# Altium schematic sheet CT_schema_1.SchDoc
size 511 x 447 mm
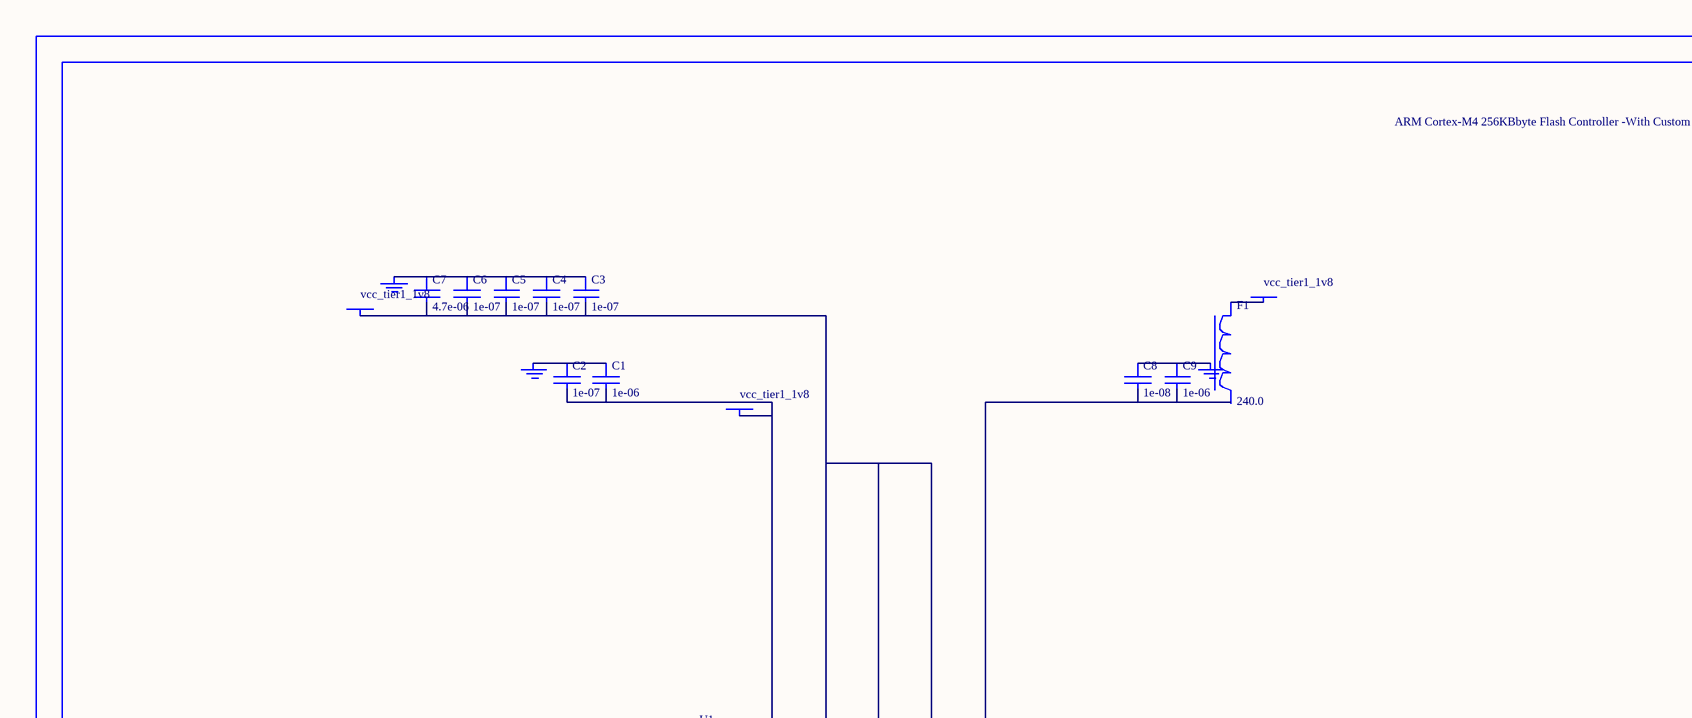
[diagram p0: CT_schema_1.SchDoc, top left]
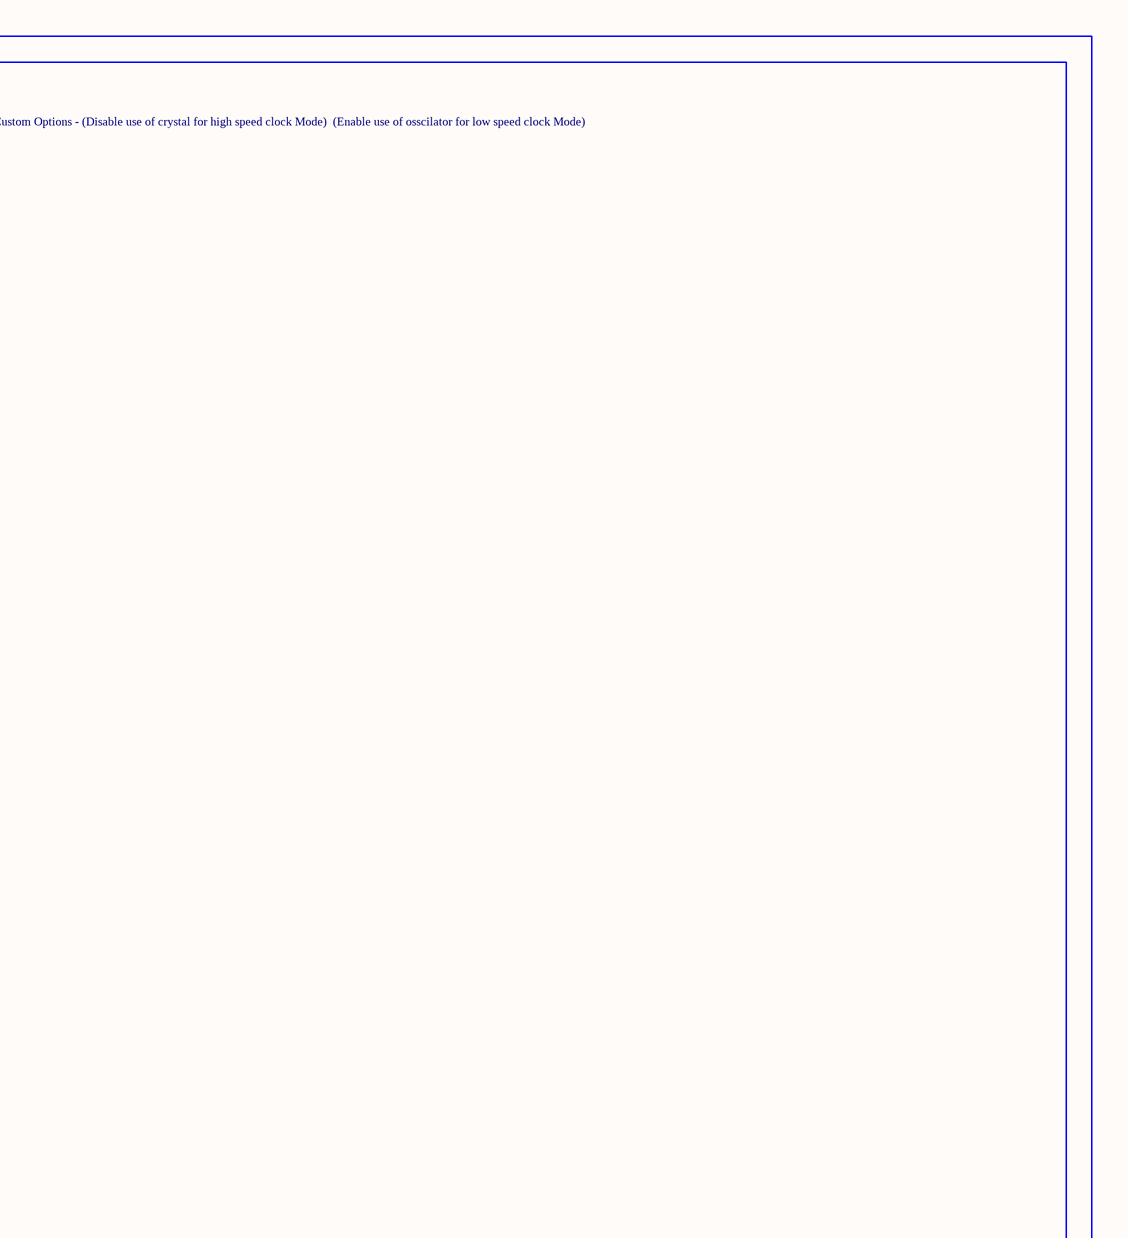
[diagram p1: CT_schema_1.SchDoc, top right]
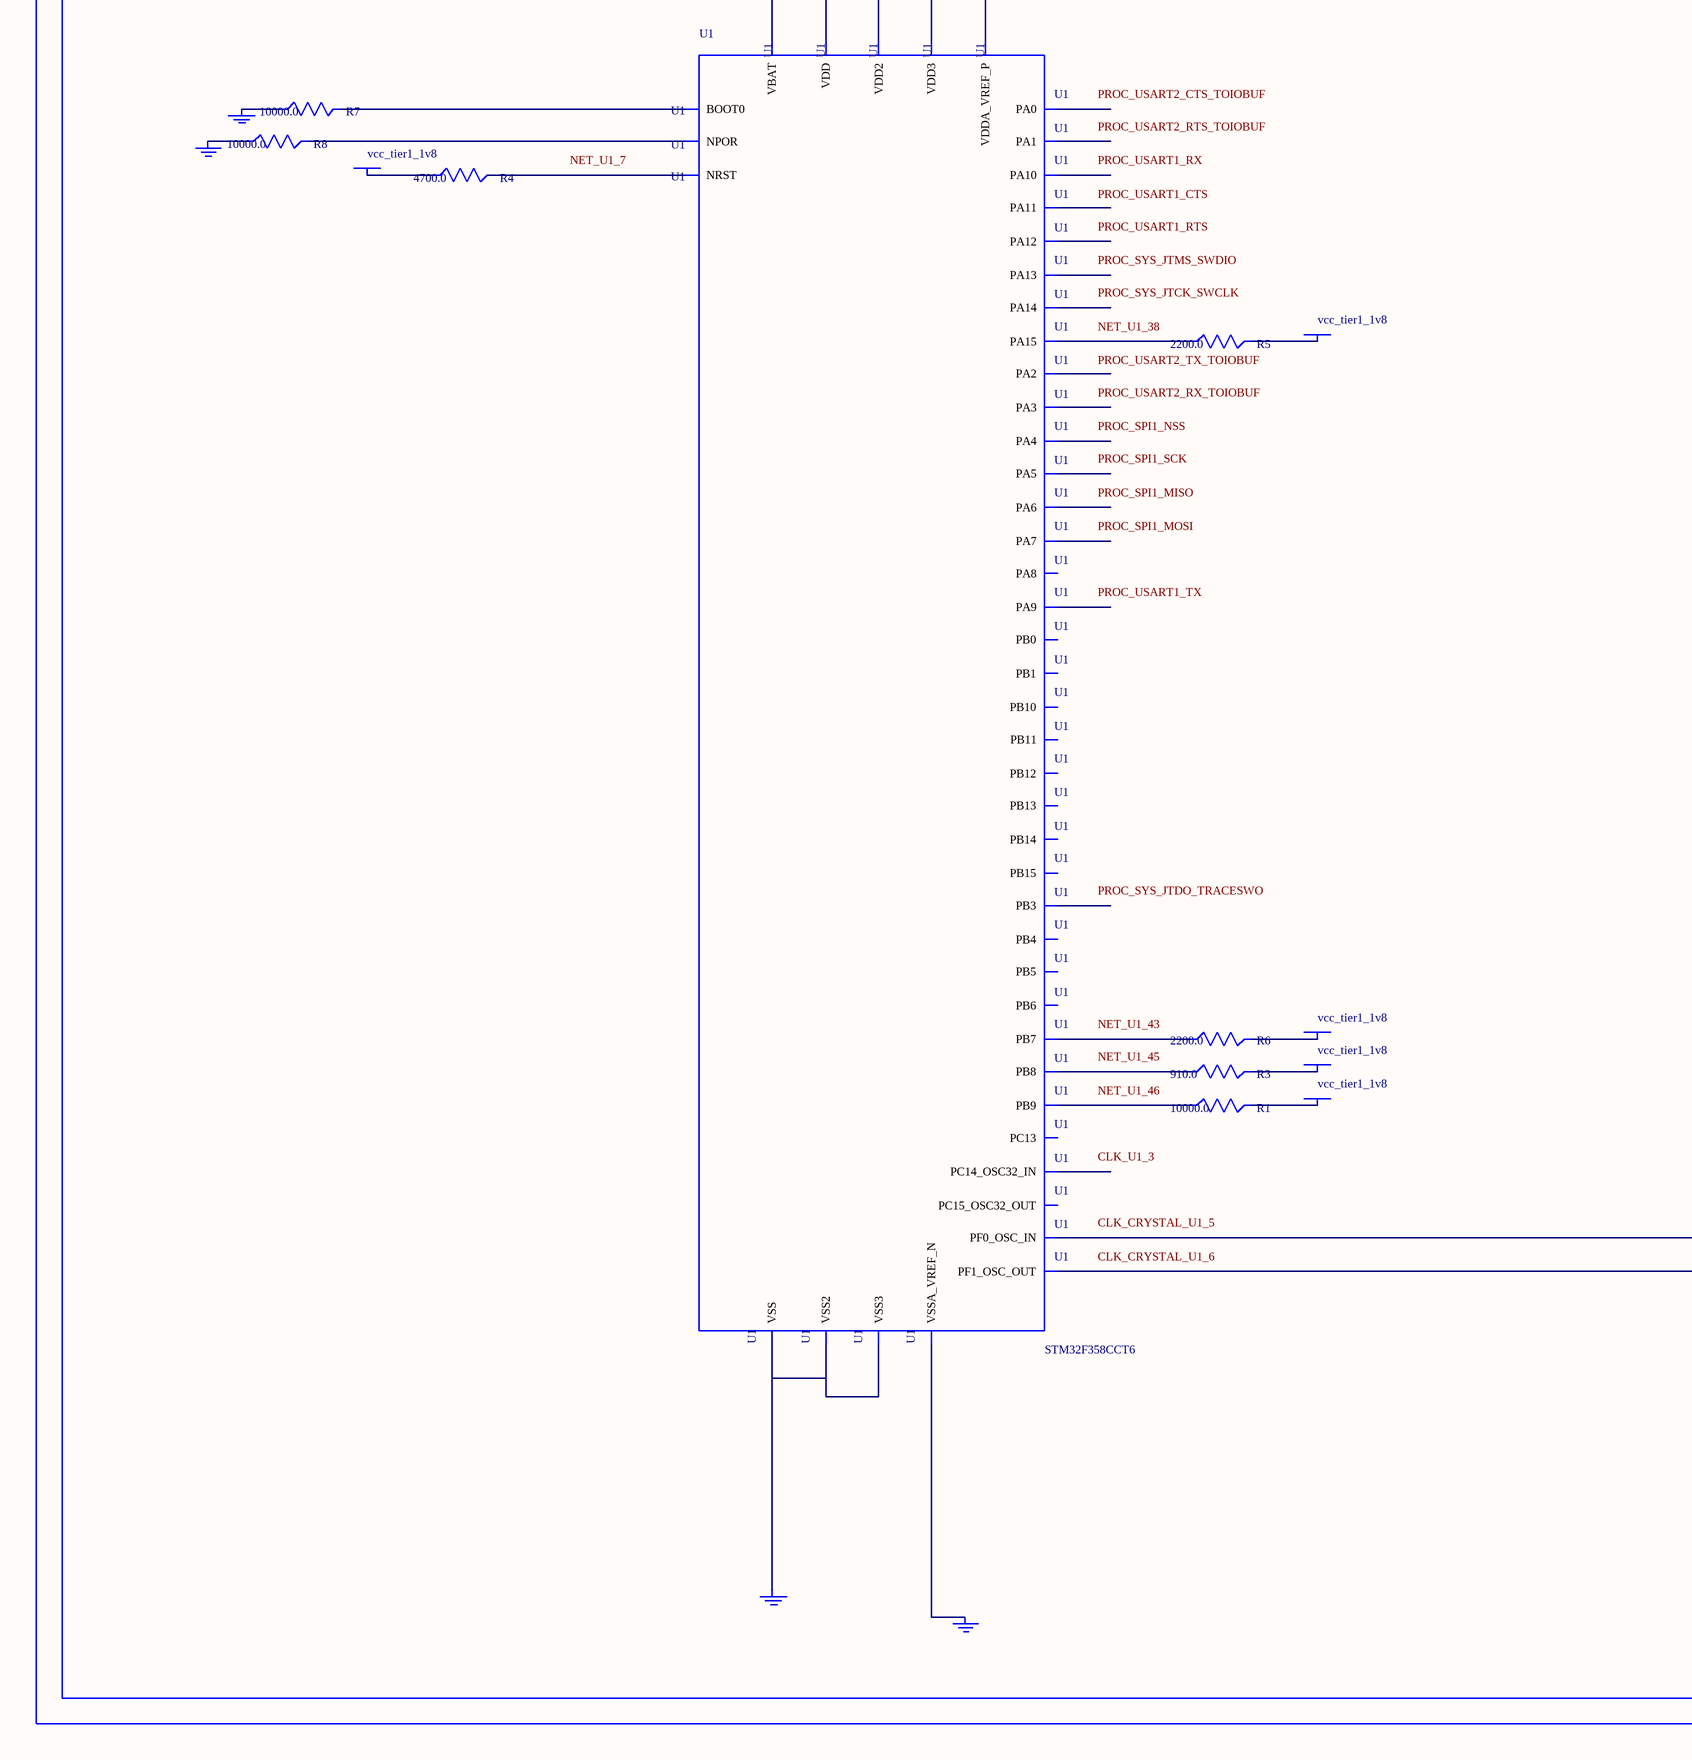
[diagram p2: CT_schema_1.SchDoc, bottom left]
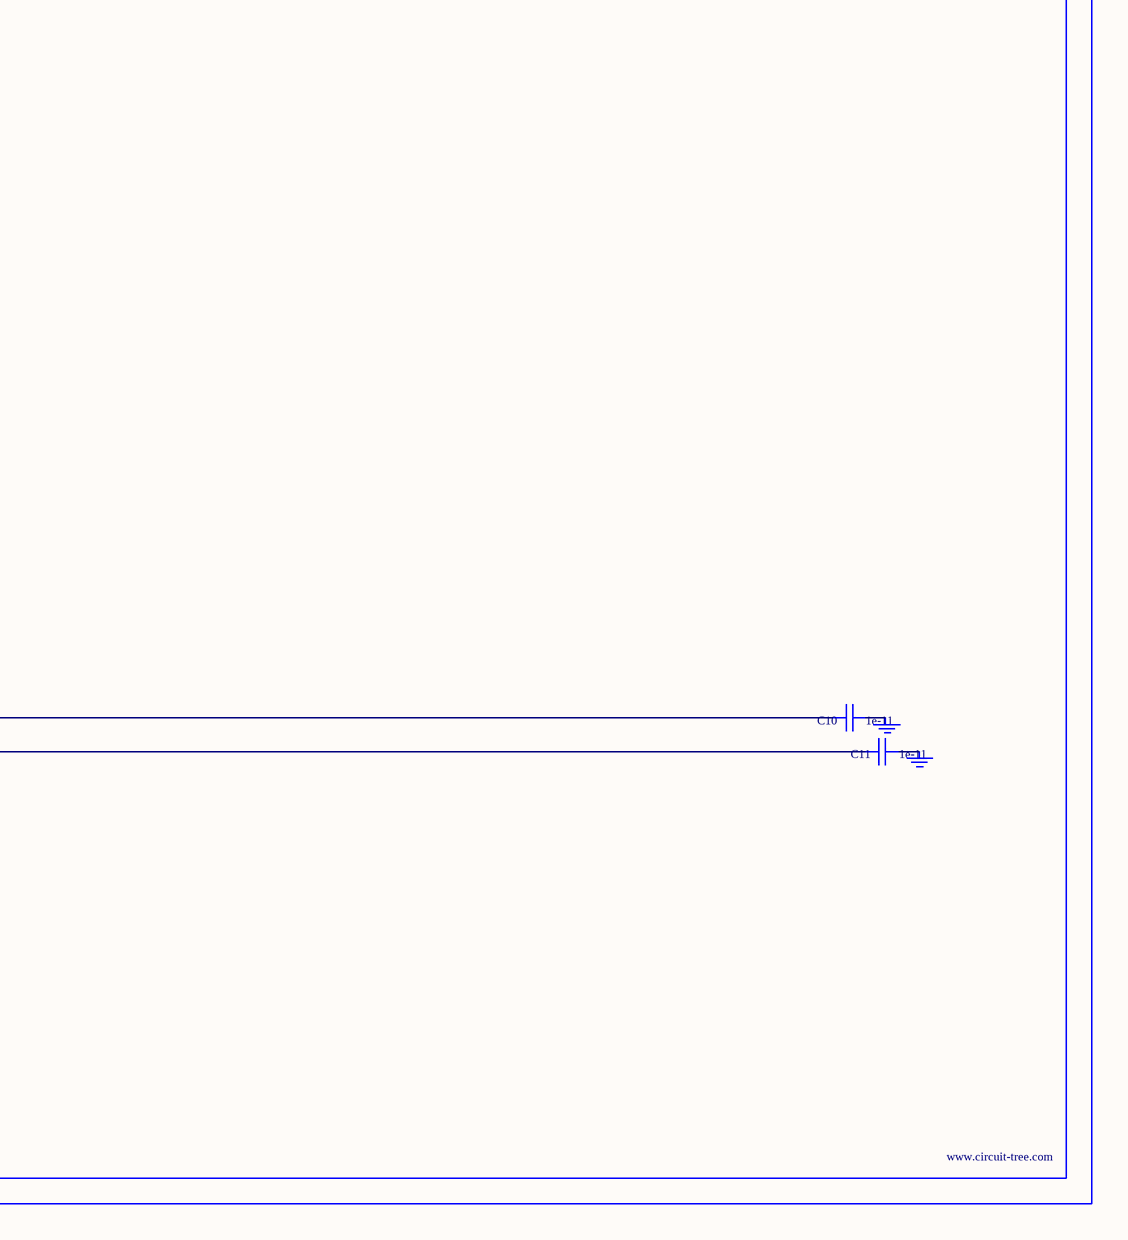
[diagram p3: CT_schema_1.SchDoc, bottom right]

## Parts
BORDER0  (no value)
C1  1e-06  [C0603]
C2  1e-07  [C0603]
C3  1e-07  [C0603]
C4  1e-07  [C0603]
C5  1e-07  [C0603]
C6  1e-07  [C0603]
C7  4.7e-06  [C0603]
C8  1e-08  [C0603]
C9  1e-06  [C0603]
C10  1e-11  [C0402]
C11  1e-11  [C0402]
F1  240.0  [L0603]
GND_INSTANCE_0_0  (no value)
GND_INSTANCE_0_1  (no value)
GND_INSTANCE_0_2  (no value)
GND_INSTANCE_0_3  (no value)
GND_INSTANCE_0_4  (no value)
GND_INSTANCE_0_5  (no value)
GND_INSTANCE_0_6  (no value)
GND_INSTANCE_0_7  (no value)
GND_INSTANCE_0_8  (no value)
POWER_INSTANCE_0_0  vcc_tier1_1v8
POWER_INSTANCE_0_1  vcc_tier1_1v8
POWER_INSTANCE_0_2  vcc_tier1_1v8
POWER_INSTANCE_0_3  vcc_tier1_1v8
POWER_INSTANCE_0_4  vcc_tier1_1v8
POWER_INSTANCE_0_5  vcc_tier1_1v8
POWER_INSTANCE_0_6  vcc_tier1_1v8
POWER_INSTANCE_0_7  vcc_tier1_1v8
R1  10000.0  [R0603]
R3  910.0  [R0603]
R4  4700.0  [R0603]
R5  2200.0  [R0603]
R6  2200.0  [R0603]
R7  10000.0  [R0603]
R8  10000.0  [R0603]
U1  STM32F358CCT6  [LQFP48]

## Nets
NetC1_1: C1.1 C2.1 GND_INSTANCE_0_0.0(GND)
NetC1_2: C1.2 C2.2 POWER_INSTANCE_0_0.0(PWR) U1.1(VBAT)
NetC3_1: C3.1 C4.1 C5.1 C6.1 C7.1 GND_INSTANCE_0_6.0(GND)
NetC3_2: C3.2 C4.2 C5.2 C6.2 C7.2 POWER_INSTANCE_0_2.0(PWR) U1.24(VDD) U1.36(VDD2) U1.48(VDD3)
NetC8_1: C8.1 C9.1 GND_INSTANCE_0_4.0(GND)
NetC8_2: C8.2 C9.2 U1.9(VDDA_VREF_P)
NetC10_1: C10.1 GND_INSTANCE_0_1.0(GND)
NetC10_2: C10.2 U1.5(PF0_OSC_IN)
NetC11_1: C11.1 GND_INSTANCE_0_2.0(GND)
NetC11_2: C11.2 U1.6(PF1_OSC_OUT)
NetF1_1: F1.1 POWER_INSTANCE_0_1.0(PWR)
NetGND_INSTANCE_0_3_0: GND_INSTANCE_0_3.0(GND) U1.8(VSSA_VREF_N)
NetGND_INSTANCE_0_5_0: GND_INSTANCE_0_5.0(GND) R8.1
NetGND_INSTANCE_0_7_0: GND_INSTANCE_0_7.0(GND) R7.1
NetGND_INSTANCE_0_8_0: GND_INSTANCE_0_8.0(GND) U1.23(VSS) U1.35(VSS2) U1.47(VSS3)
NetPOWER_INSTANCE_0_3_0: POWER_INSTANCE_0_3.0(PWR) R4.1
NetPOWER_INSTANCE_0_4_0: POWER_INSTANCE_0_4.0(PWR) R5.2
NetPOWER_INSTANCE_0_5_0: POWER_INSTANCE_0_5.0(PWR) R6.2
NetPOWER_INSTANCE_0_6_0: POWER_INSTANCE_0_6.0(PWR) R3.2
NetPOWER_INSTANCE_0_7_0: POWER_INSTANCE_0_7.0(PWR) R1.2
NetR1_1: R1.1 U1.46(PB9)
NetR3_1: R3.1 U1.45(PB8)
NetR4_2: R4.2 U1.7(NRST)
NetR5_1: R5.1 U1.38(PA15)
NetR6_1: R6.1 U1.43(PB7)
NetR7_2: R7.2 U1.44(BOOT0)
NetR8_2: R8.2 U1.20(NPOR)

Not connected (* = marked no-connect by the designer): F1 2; U1 2(PC13) 3(PC14_OSC32_IN) 4(PC15_OSC32_OUT) 10(PA0) 11(PA1) 12(PA2) 13(PA3) 14(PA4) 15(PA5) 16(PA6) 17(PA7) 18(PB0) 19(PB1) 21(PB10) 22(PB11) 25(PB12) 26(PB13) 27(PB14) 28(PB15) 29(PA8) 30(PA9) 31(PA10) 32(PA11) 33(PA12) 34(PA13) 37(PA14) 39(PB3) 40(PB4) 41(PB5) 42(PB6)

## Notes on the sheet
- Labels drawn without touching a wire or pin: CLK_CRYSTAL_U1_5, CLK_CRYSTAL_U1_6, CLK_U1_3, NET_U1_7, NET_U1_38, NET_U1_43, NET_U1_45, NET_U1_46, PROC_SPI1_MISO, PROC_SPI1_MOSI, PROC_SPI1_NSS, PROC_SPI1_SCK, PROC_SYS_JTCK_SWCLK, PROC_SYS_JTDO_TRACESWO, PROC_SYS_JTMS_SWDIO, PROC_USART1_CTS, PROC_USART1_RTS, PROC_USART1_RX, PROC_USART1_TX, PROC_USART2_CTS_TOIOBUF, PROC_USART2_RTS_TOIOBUF, PROC_USART2_RX_TOIOBUF, PROC_USART2_TX_TOIOBUF

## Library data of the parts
BORDER0 = BORDER_PAGE0
C1 C9 = C0603C105K3RACTU
C2-C6 = 06035C104K4Z2A
C7 = GRM188R6YA475KE15D
C8 = 06035C103K4Z2A
C10 C11 = C0402C100K3GACTU
F1 = Z0603C241ASMST
GND_INSTANCE_0_0-GND_INSTANCE_0_8 = GND
POWER_INSTANCE_0_0-POWER_INSTANCE_0_7 = PWR
R1 R7 R8 = RC0603JR-0710KL
R3 = RC0603JR-07910RL
R4 = RC0603JR-074K7L
R5 R6 = RC0603JR-072K2L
